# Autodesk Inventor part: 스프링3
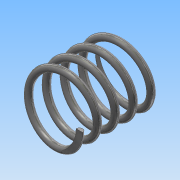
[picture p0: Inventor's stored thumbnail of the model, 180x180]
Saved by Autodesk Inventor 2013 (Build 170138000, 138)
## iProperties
Created: 2016-10
Part Number: 스프링3
Material: 강철, 탄소
Document SubType Name: Modeling
Designer: Administrator
Mass: 4.26354 g
Surface Area: 11.2836 cm^2
Volume: 0.541746 cm^3
Density: 7.87 g/cm^3
Author: Administrator
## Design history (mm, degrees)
sketch "스케치1"
  geometry: L1 (0, 0)-(0, 16.67); L2 (0, 16.67)-(25, 16.67); C1 r 1 at (9, 0)
  constraints: 4 end point, 1 centre point, 1 horizontal alignment, 1 perpendicular, 1 vertical
  dimensions: "d0" = 16.66987 distance of L1.start L1.end (derived); "d1" = 25 distance of L1.end L2.end; "d2" = 2 diameter of C1; "d3" = 18 diameter of C1.centre L1
feature "코일1" sketch "스케치1" pitch "d4" = 10; turns "d6" = 5; dims "d5" = 27, "d7" = 0, angle "d8" = 90 deg, angle "d9" = 90 deg, "d10" = 0, "d11" = 0
sketch "스케치2"
  geometry: L1 (16.67, 12)-(0, 12); L2 (0, 12)-(0, -12); L3 (0, -12)-(16.67, -12); L4 (16.67, -12)-(16.67, 12); 2 further points
  constraints: 8 end point, 2 parallel, 1 coincident, 1 horizontal, 1 midpoint, 1 perpendicular
  dimensions: "d12" = 16.66987 distance of L1.start L1.end (derived); "d14" = 24 distance of L3.end L1.start
extrude "돌출1" sketch "스케치2" stored distance "d15" = 0; taper "d16" = 0 deg
node "솔리드1"
